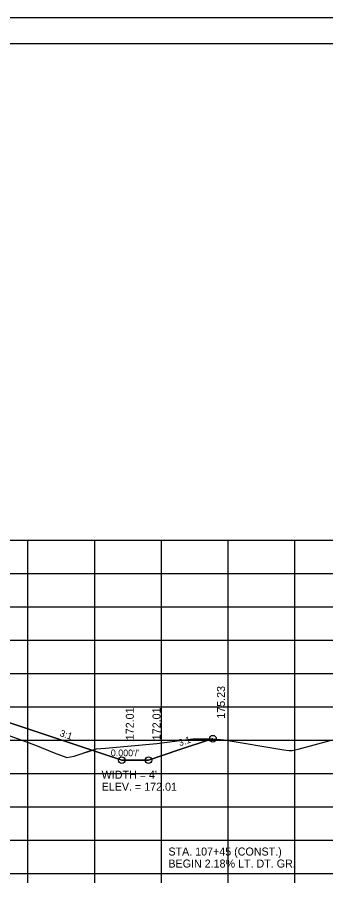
# Model space of a CAD drawing. Extents: x 1372132 to 1372465, y 380083 to 381790.
# Drawn here: x 1372330.4 to 1372376.6, y 381019.7 to 381150.2 of the extents above; entities that cross this region are included whole.
import ezdxf

# ---------------------------------------------------------------- set-up
doc = ezdxf.new("R2010")
doc.units = 0
for name, color, linetype in [('R_Axis', 7, 'Continuous'), ('R_Border', 7, 'Continuous'), ('R_Dimension', 7, 'Continuous'), ('R_Draft', 7, 'Continuous'), ('R_Exist Surface', 7, 'Continuous'), ('R_Fin Surface', 7, 'Continuous'), ('R_Grid', 7, 'Continuous'), ('R_No Plot', 7, 'Continuous'), ('R_Xsect Elev', 7, 'Continuous'), ('R_Xsect Slope', 7, 'Continuous')]:
    doc.layers.add(name, color=color, linetype=linetype)

msp = doc.modelspace()

# ---------------------------------------------------------------- linework, layer by layer
at = {"layer": 'R_Axis'}
for p, q in [((1372162.01, 381021.83), (1372442.01, 381021.83)), ((1372332.01, 381020.43), (1372332.01, 381021.83)), ((1372342.01, 381020.43), (1372342.01, 381021.83)), ((1372352.01, 381020.43), (1372352.01, 381021.83)), ((1372362.01, 381020.43), (1372362.01, 381021.83)), ((1372372.01, 381020.43), (1372372.01, 381021.83))]:
    msp.add_line(p, q, dxfattribs=at)
at = {"layer": 'R_Border'}
msp.add_line((1372144.01, 381146.29), (1372460.19, 381146.29), dxfattribs=at)
at = {"layer": 'R_Exist Surface'}
msp.add_lwpolyline([(1372320.06, 381045.84), (1372333.14, 381041.1), (1372335.96, 381039.94), (1372337.86, 381039.25), (1372338.93, 381039.46), (1372342.28, 381040.56), (1372343.64, 381040.64), (1372351.33, 381041.32), (1372356.69, 381042.06), (1372359.72, 381042.05), (1372361.42, 381041.88), (1372370.37, 381040.4), (1372371.16, 381040.28), (1372371.38, 381040.28), (1372371.59, 381040.28), (1372372.5, 381040.48), (1372377.27, 381041.77)], dxfattribs=at)
at = {"layer": 'R_Fin Surface'}
msp.add_lwpolyline([(1372234.7, 381043.31), (1372241.96, 381040.9), (1372249.04, 381038.53), (1372257.04, 381038.53), (1372267.08, 381041.86), (1372277.01, 381045.19), (1372282.65, 381046.6), (1372287.01, 381047.69), (1372291.01, 381047.85), (1372302.01, 381048.07), (1372313.01, 381047.85), (1372317.01, 381047.69), (1372321.38, 381046.6), (1372327.01, 381045.19), (1372336.47, 381042.02), (1372346.07, 381038.83), (1372350.07, 381038.83), (1372354.63, 381040.37), (1372359.6, 381042.02), (1372359.73, 381042.05)], dxfattribs=at)
at = {"layer": 'R_Grid'}
for p, q in [((1372162.01, 381071.83), (1372442.01, 381071.83)), ((1372332.01, 381021.83), (1372332.01, 381071.83)), ((1372342.01, 381021.83), (1372342.01, 381071.83)), ((1372352.01, 381021.83), (1372352.01, 381071.83)), ((1372362.01, 381021.83), (1372362.01, 381071.83)), ((1372372.01, 381021.83), (1372372.01, 381071.83)), ((1372162.01, 381066.83), (1372442.01, 381066.83)), ((1372162.01, 381061.83), (1372442.01, 381061.83)), ((1372162.01, 381056.83), (1372442.01, 381056.83)), ((1372162.01, 381051.83), (1372442.01, 381051.83)), ((1372162.01, 381046.83), (1372442.01, 381046.83)), ((1372162.01, 381041.83), (1372442.01, 381041.83)), ((1372162.01, 381036.83), (1372442.01, 381036.83)), ((1372162.01, 381031.83), (1372442.01, 381031.83)), ((1372162.01, 381026.83), (1372442.01, 381026.83)), ((1372162.01, 381021.83), (1372442.01, 381021.83))]:
    msp.add_line(p, q, dxfattribs=at)
at = {"layer": 'R_No Plot'}
msp.add_line((1372131.61, 381150.18), (1372464.95, 381150.18), dxfattribs=at)
for points in [[(1372131.61, 381150.18), (1372464.95, 381150.18), (1372464.95, 380936.84), (1372131.61, 380936.84)], [(1372377.93, 381146.29), (1372377.93, 381136.41), (1372413.67, 381136.41), (1372413.67, 381133.49), (1372436.87, 381133.49), (1372436.87, 381109.15), (1372460.19, 381109.15), (1372460.19, 380940.83), (1372144.01, 380940.83), (1372144.01, 381146.29)], [(1372317.36, 381046.68), (1372317.93, 381046.57), (1372318.37, 381046.48), (1372320.06, 381045.84), (1372333.14, 381041.1), (1372335.96, 381039.94), (1372337.86, 381039.25), (1372338.93, 381039.46), (1372341.58, 381040.33), (1372336.47, 381042.02), (1372327.01, 381045.19), (1372321.38, 381046.6)], [(1372341.58, 381040.33), (1372342.28, 381040.56), (1372343.64, 381040.64), (1372351.33, 381041.32), (1372356.69, 381042.06), (1372359.72, 381042.05), (1372359.73, 381042.05), (1372359.6, 381042.02), (1372354.63, 381040.37), (1372350.07, 381038.83), (1372346.07, 381038.83)]]:
    msp.add_lwpolyline(points, close=True, dxfattribs=at)
for centre in [(1372359.73, 381042.05), (1372346.07, 381038.83), (1372350.07, 381038.83)]:
    msp.add_circle(centre, 0.5, dxfattribs=at)

# ---------------------------------------------------------------- texts
at = {"layer": 'R_Dimension'}
for s, p in [("WIDTH = 4'", (1372343.05, 381036.06)), ('ELEV. = 172.01', (1372343.05, 381034.26))]:
    msp.add_text(s, height=1.2, dxfattribs=at).set_placement(p)
at = {"layer": 'R_Draft'}
for s, p in [('STA. 107+45 (CONST.)', (1372353.05, 381024.54)), ('BEGIN 2.18% LT. DT. GR.', (1372353.05, 381022.74))]:
    msp.add_text(s, height=1.2, dxfattribs=at).set_placement(p)
at = {"layer": 'R_Xsect Elev'}
for s, p in [('175.23', (1372361.53, 381045.05)), ('172.01', (1372347.87, 381041.83)), ('172.01', (1372351.87, 381041.83))]:
    msp.add_text(s, height=1.2, rotation=90, dxfattribs=at).set_placement(p)
at = {"layer": 'R_Xsect Slope'}
for s, rotation, p in [('3:1', 341.5668, (1372336.7, 381042.48)), ('3:1', 18.4349, (1372354.74, 381040.92)), ("0.000'/'", 360, (1372344.42, 381039.43))]:
    msp.add_text(s, height=1, rotation=rotation, dxfattribs=at).set_placement(p)

doc.saveas('drawing.dxf')
